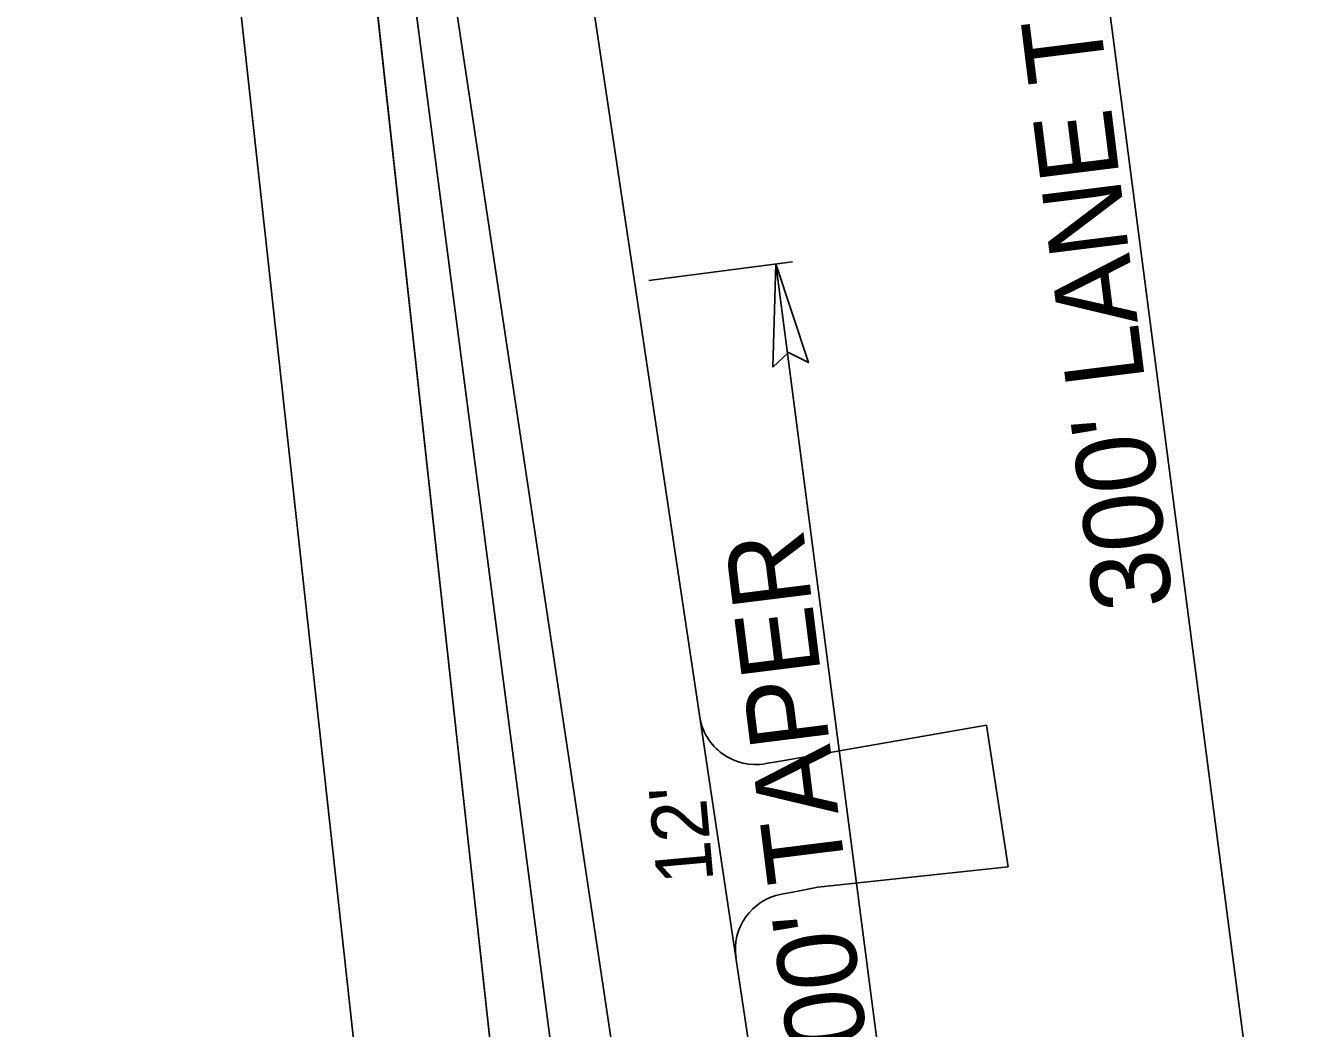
# Model space of a CAD drawing. Extents: x 2367848 to 2369479, y 800728 to 808616.
# Drawn here: x 2368315.2 to 2368427.3, y 808105 to 808193.7 of the extents above; entities that cross this region are included whole.
import ezdxf

# ---------------------------------------------------------------- set-up
doc = ezdxf.new("R2010")
doc.units = 0
for name, color, linetype in [('Prop Dimension', 7, 'Continuous'), ('Prop EOT', 7, 'Continuous'), ('Prop Horizontal Alignment', 7, 'Continuous'), ('Prop Lane Lines', 7, 'Continuous'), ('Prop Paint Stripe', 7, 'Continuous'), ('Prop Terminator CELL', 7, 'Continuous')]:
    doc.layers.add(name, color=color, linetype=linetype)

msp = doc.modelspace()

# ---------------------------------------------------------------- linework, layer by layer
at = {"layer": 'Prop Dimension'}
for p, q in [((2368387.64, 808375.11), (2368426.37, 808077.62)), ((2368370.36, 808171.17), (2368383.06, 808172.82)), ((2368381.58, 808172.63), (2368394.49, 808073.47))]:
    msp.add_line(p, q, dxfattribs=at)
at = {"layer": 'Prop EOT'}
for p, q in [((2368339.44, 808368.83), (2368383.94, 808072.1)), ((2368348.25, 808067.45), (2368315.58, 808365.73)), ((2368400.2, 808131.84), (2368381.64, 808128.6)), ((2368402.11, 808119.3), (2368400.2, 808131.84)), ((2368381.64, 808128.6), (2368380.67, 808128.43)), ((2368385.29, 808117.5), (2368402.11, 808119.3)), ((2368382.08, 808116.89), (2368383.37, 808117.13)), ((2368383.37, 808117.13), (2368385.29, 808117.5))]:
    msp.add_line(p, q, dxfattribs=at)
for centre, start, end in [((2368379.8, 808133.35), 188.5292, 279.9123), ((2368383.01, 808111.98), 100.7621, 188.5292)]:
    msp.add_arc(centre, 5, start, end, dxfattribs=at)
at = {"layer": 'Prop Horizontal Alignment'}
msp.add_line((2368427.27, 807599.89), (2368315.24, 808460.34), dxfattribs=at)
at = {"layer": 'Prop Lane Lines'}
for p, q in [((2368360.2, 808068.57), (2368327.53, 808366.85)), ((2368327.59, 808366.86), (2368372.04, 808070.55)), ((2368360.2, 808068.57), (2368349.27, 808168.42))]:
    msp.add_line(p, q, dxfattribs=at)
at = {"layer": 'Prop Paint Stripe'}
for p, q in [((2368327.53, 808366.85), (2368349.27, 808168.42)), ((2368372.04, 808070.55), (2368327.59, 808366.86)), ((2368372.04, 808070.55), (2368327.59, 808366.86)), ((2368349.27, 808168.42), (2368360.2, 808068.57))]:
    msp.add_line(p, q, dxfattribs=at)
msp.add_lwpolyline([(2368327.53, 808366.85), (2368349.27, 808168.42), (2368360.2, 808068.57)], dxfattribs=at)
at = {"layer": 'Prop Terminator CELL'}
msp.add_lwpolyline([(2368381.33, 808163.5), (2368381.58, 808172.63), (2368384.46, 808163.9), (2368382.71, 808164.81)], close=True, dxfattribs=at)

# ---------------------------------------------------------------- texts
at = {"layer": 'Prop Dimension'}
for s, height, rotation, p in [("300' LANE TAPER LT & RT", 7, 97.1063, (2368416.71, 808142.47)), ("100' TAPER", 7, 97.1063, (2368390.31, 808098.53)), ("12'", 5, 95.1308, (2368376.09, 808118.04))]:
    msp.add_text(s, height=height, rotation=rotation, dxfattribs=at).set_placement(p)

doc.saveas('drawing.dxf')
